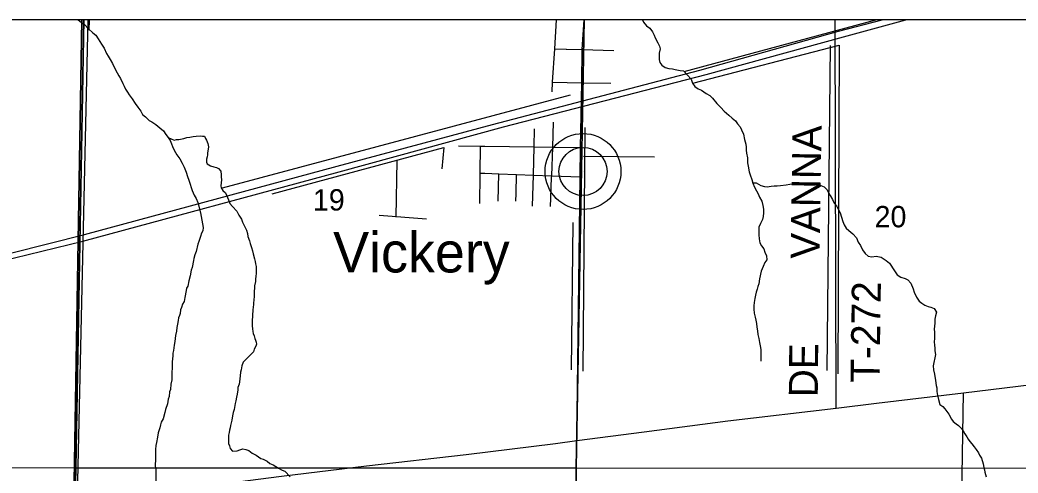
# Model space of a CAD drawing. Extents: x -8.5 to 18.7, y -20.3 to 7.
# Drawn here: x 11.462 to 15.375, y 5.162 to 6.938 of the extents above; entities that cross this region are included whole.
import ezdxf

# ---------------------------------------------------------------- set-up
doc = ezdxf.new("R2010")
doc.units = 0
for name, color, linetype in [('Default', 7, 'Continuous'), ('GM_X_Corporation', 7, 'Continuous'), ('GM_X_County_Road', 7, 'Continuous'), ('GM_X_Minor_River', 7, 'Continuous'), ('GM_X_Rail_Line', 7, 'Continuous'), ('GM_X_Section', 7, 'Continuous'), ('GM_X_Section_Text', 7, 'Continuous'), ('GM_X_State_Route', 7, 'Continuous'), ('GM_X_Township_Road', 7, 'Continuous'), ('GM_X_Township_Road_Text', 7, 'Continuous'), ('GM_X_Unincorporated', 7, 'Continuous'), ('GM_X_Unincorporated_Location', 7, 'Continuous'), ('GM_X_Unincorporated_Text', 7, 'Continuous'), ('SH_Cut_Line', 7, 'Continuous')]:
    doc.layers.add(name, color=color, linetype=linetype)

msp = doc.modelspace()

# ---------------------------------------------------------------- linework, layer by layer
at = {"layer": 'Default'}
for points in [[(11.7119, 6.938), (9.7054, 6.938), (9.6798, 5.1845), (11.681, 5.1825)], [(13.674, 6.938), (11.7119, 6.938), (11.681, 5.1825), (13.6421, 5.1822)], [(15.6554, 6.938), (13.674, 6.938), (13.6421, 5.1822), (15.6471, 5.1817)]]:
    msp.add_lwpolyline(points, close=True, dxfattribs=at)
at = {"layer": 'GM_X_Corporation'}
msp.add_lwpolyline([(3.6318, 1.1236), (5.043, 1.1473), (5.1251, 1.1484), (7.5383, 1.181), (7.59, 1.1818), (9.5569, 1.2131), (11.5871, 1.2389), (11.6132, 2.2462), (11.64, 3.2551), (11.6653, 4.2586), (11.6686, 4.5917), (11.6689, 4.6186), (11.6732, 5.0475), (11.7049, 6.938), (-0.1911, 6.938)], dxfattribs=at)
msp.add_lwpolyline([(18.7413, 1.1834), (18.7413, 6.938), (11.7049, 6.938), (11.6732, 5.0475), (11.6689, 4.6186), (11.6686, 4.5917), (11.6653, 4.2586), (11.64, 3.2551), (11.6132, 2.2462), (11.5871, 1.2389), (13.587, 1.2234), (15.5804, 1.208), (17.3261, 1.1944), (18.0915, 1.1885)], close=True, dxfattribs=at)
at = {"layer": 'GM_X_County_Road'}
for p, q in [((11.6869, 5.048), (11.7294, 6.938)), ((13.6358, 4.2197), (13.645, 5.2895))]:
    msp.add_line(p, q, dxfattribs=at)
msp.add_lwpolyline([(13.645, 5.2895), (13.6582, 6.3234), (13.6599, 6.4386), (13.6644, 6.6919), (13.6668, 6.8218), (13.6743, 6.938)], dxfattribs=at)
at = {"layer": 'GM_X_Minor_River'}
for p, q in [((11.7332, 6.8978), (11.7341, 6.938)), ((14.0662, 6.7359), (14.8175, 6.938)), ((14.0996, 6.69), (14.6734, 6.8391)), ((14.6265, 5.5642), (14.6405, 6.8383)), ((14.6734, 6.8391), (14.6682, 5.5509)), ((14.6734, 6.8391), (14.6734, 6.8391)), ((12.2558, 6.2802), (13.62, 6.6444)), ((13.67, 5.5617), (13.6786, 6.5159)), ((12.4511, 6.2567), (13.1239, 6.4386)), ((13.1239, 6.4386), (13.1165, 6.355)), ((13.1239, 6.4386), (13.1239, 6.4386)), ((12.9392, 6.3878), (12.9353, 6.1655)), ((13.6718, 6.4045), (13.95, 6.4014)), ((12.8702, 6.1733), (13.056, 6.1589)), ((13.624, 5.5667), (13.6312, 6.1439))]:
    msp.add_line(p, q, dxfattribs=at)
for points in [[(11.6893, 6.938), (11.7024, 6.9278), (11.7146, 6.9203), (11.7307, 6.9028), (11.7474, 6.887), (11.7589, 6.8779), (11.7688, 6.8635), (11.7818, 6.843), (11.7925, 6.8271), (11.801, 6.8067), (11.8071, 6.7961), (11.8148, 6.7824), (11.824, 6.7673), (11.8309, 6.7536), (11.8431, 6.7309), (11.8493, 6.7187), (11.8554, 6.7081), (11.8653, 6.6892), (11.87, 6.6786), (11.8761, 6.6664), (11.8837, 6.6551), (11.8899, 6.6445), (11.9013, 6.6286), (11.9128, 6.6104), (11.9235, 6.596), (11.935, 6.5801), (11.9426, 6.5679), (11.9533, 6.5581), (11.9678, 6.5445), (11.9792, 6.5385), (11.9945, 6.5279), (12.0097, 6.515), (12.0242, 6.5029), (12.0334, 6.4893), (12.0425, 6.4772)], [(13.9034, 6.938), (13.9069, 6.9296), (13.9184, 6.9152), (13.9313, 6.9061), (13.942, 6.8917), (13.9482, 6.8789), (13.9528, 6.8682), (13.9627, 6.8485), (13.9689, 6.8356), (13.972, 6.825), (13.9683, 6.8075), (13.9684, 6.7825), (13.9707, 6.7718), (13.9784, 6.7605), (13.9921, 6.7514), (14.0065, 6.7477), (14.0202, 6.7462), (14.0308, 6.744), (14.0506, 6.7403), (14.0635, 6.7388), (14.0795, 6.7214), (14.094, 6.7055), (14.0994, 6.6903), (14.1078, 6.6774), (14.1208, 6.6676), (14.1337, 6.6631), (14.152, 6.6502), (14.1665, 6.642), (14.1772, 6.6314), (14.1947, 6.6109), (14.21, 6.5943), (14.2237, 6.5806), (14.2413, 6.5648), (14.255, 6.5527), (14.2679, 6.5421), (14.2748, 6.5307), (14.2855, 6.5194), (14.2909, 6.508)], [(14.2909, 6.508), (14.2993, 6.4905), (14.3032, 6.4701), (14.3079, 6.4518), (14.3087, 6.4389), (14.3095, 6.4283), (14.3111, 6.4154), (14.3142, 6.3979), (14.3151, 6.3782), (14.3174, 6.3653), (14.3206, 6.3433), (14.3244, 6.3311), (14.3313, 6.3122), (14.336, 6.2985), (14.3421, 6.2833), (14.3498, 6.2689), (14.3567, 6.2568), (14.3621, 6.2432), (14.3705, 6.2272), (14.3751, 6.2113), (14.3767, 6.1961), (14.3776, 6.1825), (14.3754, 6.1673), (14.3731, 6.1558), (14.3649, 6.1399), (14.3596, 6.1262), (14.3589, 6.111), (14.359, 6.0958), (14.3606, 6.0798), (14.363, 6.0639), (14.3699, 6.0533), (14.3783, 6.0412), (14.3829, 6.0275), (14.389, 6.0139), (14.3899, 5.9979), (14.3831, 5.9873), (14.3756, 5.972), (14.3688, 5.9538), (14.3614, 5.9234), (14.3585, 5.9044), (14.3547, 5.8937), (14.3525, 5.8831), (14.348, 5.8709), (14.3458, 5.8595), (14.3428, 5.8458), (14.3406, 5.8306), (14.3399, 5.8177), (14.34, 5.804), (14.3408, 5.7888), (14.3447, 5.7729), (14.3478, 5.7608), (14.3494, 5.7478), (14.351, 5.7334), (14.3533, 5.7198), (14.3549, 5.7046), (14.3588, 5.6894), (14.3619, 5.6735), (14.3643, 5.6606), (14.3666, 5.6461), (14.3668, 5.6012)], [(12.0425, 6.4772), (12.0669, 6.4666), (12.0752, 6.469), (12.0851, 6.4698), (12.104, 6.4729), (12.1162, 6.4767), (12.1283, 6.479), (12.1412, 6.4814), (12.1526, 6.4822), (12.1678, 6.4845), (12.1776, 6.483), (12.1852, 6.4823), (12.1898, 6.474), (12.1929, 6.4664), (12.199, 6.4543), (12.2006, 6.4413), (12.1999, 6.4322), (12.1977, 6.417), (12.197, 6.4094), (12.1955, 6.4018), (12.1933, 6.3919), (12.1933, 6.3813), (12.1964, 6.3737), (12.2086, 6.3669), (12.2215, 6.3624), (12.2329, 6.3602), (12.2405, 6.3557), (12.2497, 6.3458), (12.2513, 6.3314), (12.2513, 6.3238), (12.2514, 6.3117), (12.2507, 6.2995), (12.25, 6.2881), (12.2508, 6.2797), (12.2577, 6.2699), (12.2676, 6.2601), (12.2722, 6.2517), (12.2799, 6.2328), (12.2845, 6.2183), (12.2952, 6.207), (12.312, 6.1888), (12.3158, 6.1813), (12.3204, 6.1729), (12.325, 6.1653), (12.3303, 6.157), (12.3342, 6.1456), (12.3411, 6.1327), (12.3495, 6.1145), (12.3534, 6.1016), (12.3557, 6.0895), (12.3619, 6.0721), (12.3642, 6.0614), (12.3696, 6.0463), (12.3735, 6.0334), (12.3758, 6.0212), (12.382, 6.0015), (12.3836, 5.9916), (12.3851, 5.9825), (12.3875, 5.9719), (12.3883, 5.9613), (12.3876, 5.943), (12.3869, 5.9347), (12.3854, 5.921), (12.3855, 5.9126), (12.3818, 5.8959), (12.3818, 5.8868), (12.3804, 5.8746), (12.3796, 5.867), (12.3797, 5.8564), (12.3783, 5.8382), (12.3776, 5.8306), (12.3768, 5.8222), (12.3754, 5.8024), (12.3747, 5.7948), (12.3732, 5.7865), (12.3733, 5.7766), (12.3718, 5.7599), (12.3719, 5.7485), (12.3727, 5.7394), (12.3735, 5.7272), (12.3743, 5.7174), (12.3766, 5.7098), (12.3805, 5.6999), (12.3828, 5.6901), (12.3859, 5.6825), (12.3882, 5.6749), (12.389, 5.6673), (12.386, 5.6597), (12.38, 5.6475), (12.3778, 5.6369)], [(12.0425, 6.4772), (12.0509, 6.4651), (12.0563, 6.4529), (12.0602, 6.4416), (12.0663, 6.4279), (12.077, 6.4097), (12.0885, 6.3931), (12.0977, 6.3771), (12.1054, 6.3605), (12.1131, 6.3415), (12.1185, 6.3248), (12.1238, 6.3104), (12.1285, 6.2945), (12.1331, 6.2808), (12.137, 6.2702), (12.1446, 6.2512), (12.1523, 6.2383), (12.1592, 6.2224), (12.1694, 6.1823)], [(14.3354, 6.3001), (14.3489, 6.3001), (14.3664, 6.2895), (14.3808, 6.2858), (14.3922, 6.2843), (14.4074, 6.2866), (14.4188, 6.2874), (14.4309, 6.2875), (14.4438, 6.2891), (14.4666, 6.2922), (14.481, 6.2938), (14.4931, 6.2953), (14.5053, 6.2954), (14.5311, 6.297), (14.5425, 6.294), (14.5531, 6.2933), (14.5668, 6.2926), (14.5797, 6.2926), (14.5911, 6.2919), (14.6025, 6.2889), (14.6154, 6.2836), (14.6261, 6.2731), (14.6322, 6.2624), (14.6384, 6.2503), (14.6475, 6.2344), (14.6544, 6.22), (14.6636, 6.2094), (14.672, 6.1942), (14.6774, 6.1821), (14.6836, 6.1647), (14.6882, 6.1487), (14.6936, 6.1351), (14.7012, 6.1222), (14.7119, 6.1131), (14.7279, 6.1003), (14.7424, 6.0836), (14.7486, 6.0677), (14.7578, 6.054), (14.7654, 6.0374), (14.7761, 6.0222), (14.7876, 6.0116), (14.802, 6.0094), (14.8187, 6.0125), (14.8392, 6.008), (14.8583, 5.9952), (14.8712, 5.9854), (14.8911, 5.9551), (14.9011, 5.9391), (14.9155, 5.9293), (14.9323, 5.9241), (14.9429, 5.9196), (14.9551, 5.9067), (14.9643, 5.8847), (14.9682, 5.871), (14.9774, 5.8521), (14.9874, 5.8362), (14.998, 5.8286), (15.0102, 5.8203), (15.0232, 5.815), (15.0338, 5.812), (15.0467, 5.8075), (15.0552, 5.7931), (15.0522, 5.7787), (15.0492, 5.765), (15.0485, 5.7498), (15.0478, 5.7377), (15.0471, 5.7263), (15.048, 5.7149), (15.0472, 5.7042), (15.0473, 5.689), (15.0466, 5.6769), (15.0482, 5.664), (15.049, 5.6518), (15.0498, 5.6412), (15.0514, 5.6275)], [(12.1694, 6.1823), (12.1805, 6.1241), (12.1783, 6.112), (12.1738, 6.1021), (12.1693, 6.0899), (12.1633, 6.0701), (12.1596, 6.0587), (12.1521, 6.0306), (12.1469, 6.0169), (12.1439, 6.0032), (12.1417, 5.9948), (12.1373, 5.9682), (12.1328, 5.9575), (12.1291, 5.9347), (12.1239, 5.9157), (12.1194, 5.8952), (12.1149, 5.8868), (12.1134, 5.8777), (12.1082, 5.8503), (12.1053, 5.8343), (12.0993, 5.8237), (12.0955, 5.8107), (12.0918, 5.8016), (12.0903, 5.7879), (12.0873, 5.7795), (12.0836, 5.7712), (12.0821, 5.7605), (12.0792, 5.7461), (12.0769, 5.7324), (12.0755, 5.7187), (12.0718, 5.7012), (12.0689, 5.6784), (12.0659, 5.6639), (12.0637, 5.6419), (12.0615, 5.632), (12.0608, 5.6221), (12.0593, 5.61), (12.0586, 5.5986), (12.0588, 5.575), (12.0573, 5.5568), (12.0574, 5.5461), (12.0567, 5.5378), (12.0567, 5.5279), (12.0538, 5.5104), (12.0516, 5.4899), (12.0486, 5.4808), (12.0472, 5.4618), (12.0434, 5.4519), (12.042, 5.4427), (12.0405, 5.4329), (12.033, 5.4115), (12.03, 5.4001), (12.0233, 5.3743), (12.0158, 5.3613), (12.0128, 5.3507), (12.0106, 5.34), (12.0039, 5.3202), (12.0009, 5.3035), (11.9972, 5.2815), (11.9942, 5.2708), (11.9936, 5.2541), (11.9937, 5.2343), (11.993, 5.2093), (11.9916, 5.1994), (11.9916, 5.1887), (11.9947, 5.1774), (11.995, 5.1257)], [(12.3778, 5.6369), (12.3373, 5.5969), (12.332, 5.5824), (12.3291, 5.5664), (12.3268, 5.5581), (12.3239, 5.5307), (12.321, 5.5109), (12.3165, 5.4972), (12.3158, 5.4881), (12.3128, 5.4714), (12.3106, 5.46), (12.3084, 5.4448), (12.3054, 5.4349), (12.301, 5.4113), (12.2973, 5.3999), (12.2951, 5.3862), (12.2929, 5.3695), (12.2899, 5.3588), (12.2869, 5.3489), (12.2854, 5.3398), (12.2832, 5.3299), (12.2817, 5.3208), (12.2795, 5.3109), (12.2788, 5.301), (12.2788, 5.2904), (12.2796, 5.2782), (12.2827, 5.2684), (12.2866, 5.2585), (12.2957, 5.2479), (12.3132, 5.2488), (12.3238, 5.2526), (12.3352, 5.2565), (12.3473, 5.255), (12.3595, 5.2505), (12.3717, 5.2407), (12.3884, 5.2324), (12.4067, 5.2196), (12.4159, 5.2166), (12.4311, 5.2083), (12.4418, 5.2), (12.4547, 5.194), (12.4752, 5.1812), (12.4905, 5.1729), (12.5004, 5.1691), (12.521, 5.148)], [(15.0514, 5.6275), (15.0431, 5.583), (15.0439, 5.5663), (15.0478, 5.5504), (15.0517, 5.5246), (15.0548, 5.5056), (15.0564, 5.4965), (15.0572, 5.4828), (15.0588, 5.4722), (15.0604, 5.4623), (15.0635, 5.4502), (15.0689, 5.4312), (15.0811, 5.4229), (15.0879, 5.4138), (15.0956, 5.4032), (15.104, 5.3934), (15.1147, 5.3737), (15.1216, 5.3646), (15.133, 5.3548), (15.1422, 5.348), (15.1536, 5.3366), (15.1605, 5.3276), (15.1674, 5.3162), (15.175, 5.3041), (15.1796, 5.295), (15.1858, 5.2859), (15.1942, 5.2761), (15.2033, 5.2655), (15.2117, 5.2541), (15.2201, 5.2412), (15.2247, 5.2329), (15.2316, 5.22), (15.2386, 5.198), (15.2417, 5.1836), (15.2433, 5.1752), (15.2456, 5.1661), (15.251, 5.1472)]]:
    msp.add_lwpolyline(points, dxfattribs=at)
at = {"layer": 'GM_X_Rail_Line'}
for points in [[(3.3492, 3.6263), (4.4113, 3.9753), (4.8681, 4.1485), (5.3383, 4.3406), (5.8491, 4.5056), (6.1923, 4.6193), (6.6809, 4.7548), (6.9366, 4.825), (7.6892, 5.0264), (8.5879, 5.2635), (9.4613, 5.4827), (11.0096, 5.9016), (11.7084, 6.0715), (12.7137, 6.343), (13.3579, 6.5187), (14.1524, 6.7238), (14.6912, 6.8722), (14.936, 6.938)], [(3.8129, 4.1403), (4.3242, 4.207), (4.4317, 4.2229), (4.6591, 4.2738), (5.1343, 4.3961), (5.6672, 4.5409), (6.9377, 4.8691), (7.6692, 5.0633), (8.6247, 5.3078), (9.4518, 5.5207), (10.9979, 5.9173), (11.7143, 6.0969), (12.7059, 6.3644), (13.315, 6.5285), (14.1271, 6.7413), (14.6717, 6.8937), (14.8429, 6.938)]]:
    msp.add_lwpolyline(points, dxfattribs=at)
at = {"layer": 'GM_X_Section'}
for points in [[(11.681, 5.1825), (11.6384, 3.2557), (9.6423, 3.2228), (9.6798, 5.1845)], [(13.6421, 5.1822), (13.6222, 3.2394), (11.6384, 3.2557), (11.681, 5.1825)], [(15.6471, 5.1817), (15.6347, 3.2252), (13.6222, 3.2394), (13.6421, 5.1822)]]:
    msp.add_lwpolyline(points, close=True, dxfattribs=at)
at = {"layer": 'GM_X_State_Route'}
msp.add_lwpolyline([(10.687, 4.9287), (10.7287, 4.9346), (10.9024, 4.9549), (11.2577, 4.9986), (11.5812, 5.0354), (11.6736, 5.0464), (11.6869, 5.048), (12.1416, 5.1052), (12.4869, 5.1498), (12.8209, 5.1899), (13.2111, 5.2354), (13.5617, 5.2783), (13.645, 5.2895), (13.909, 5.3237), (14.2377, 5.3664), (14.6621, 5.4171), (14.8198, 5.4359), (15.1611, 5.4766), (15.4293, 5.5094), (15.6511, 5.5375), (15.667, 5.5395)], dxfattribs=at)
at = {"layer": 'GM_X_Township_Road'}
for p, q in [((14.6621, 5.4171), (14.6589, 6.938)), ((13.5587, 6.8253), (13.6029, 6.8239)), ((13.6668, 6.8218), (13.7909, 6.8178)), ((13.5505, 6.6938), (13.6644, 6.6919)), ((13.6644, 6.6919), (13.7783, 6.6901)), ((13.2649, 6.2188), (13.266, 6.3313)), ((13.266, 6.3376), (13.285, 6.3369)), ((13.3365, 6.2273), (13.3392, 6.335)), ((13.4073, 6.2574), (13.4091, 6.3324)), ((13.5437, 6.24), (13.5466, 6.3225)), ((13.4065, 6.2273), (13.4073, 6.2574)), ((13.5426, 6.207), (13.5437, 6.24)), ((15.1413, 4.2248), (15.1611, 5.4766))]:
    msp.add_line(p, q, dxfattribs=at)
for points in [[(13.5482, 6.6566), (13.5505, 6.6938), (13.5587, 6.8253), (13.5659, 6.938)], [(13.6029, 6.8239), (13.6052, 6.8238), (13.6668, 6.8218)], [(13.5466, 6.3225), (13.5467, 6.3274), (13.5506, 6.44), (13.5539, 6.5371)], [(13.4718, 6.2077), (13.4748, 6.3301), (13.4774, 6.441), (13.4791, 6.5112)], [(13.181, 6.4449), (13.267, 6.4437), (13.2851, 6.4435)], [(13.266, 6.3313), (13.266, 6.3376), (13.267, 6.4437)], [(13.2851, 6.4435), (13.4774, 6.441), (13.5506, 6.44), (13.6599, 6.4386)], [(13.285, 6.3369), (13.3392, 6.335), (13.4091, 6.3324), (13.4748, 6.3301), (13.5467, 6.3274), (13.6582, 6.3234)]]:
    msp.add_lwpolyline(points, dxfattribs=at)
at = {"layer": 'GM_X_Unincorporated'}
for radius in [0.1488, 0.0943]:
    msp.add_circle((13.6696, 6.3441), radius, dxfattribs=at)
at = {"layer": 'GM_X_Unincorporated_Location'}
msp.add_line((13.6696, 6.3441), (13.6696, 6.3441), dxfattribs=at)
at = {"layer": 'SH_Cut_Line'}
msp.add_lwpolyline([(18.7413, -10.9039), (18.7413, 6.938), (-8.4587, 6.938)], dxfattribs=at)

# ---------------------------------------------------------------- texts
at = {"layer": 'GM_X_Section_Text'}
for s, p in [('19', (12.6106, 6.1911)), ('20', (14.8131, 6.1253))]:
    msp.add_text(s, height=0.08371, rotation=0, dxfattribs=at).set_placement(p)
at = {"layer": 'GM_X_Township_Road_Text'}
for s, rotation, p in [('VANNA', 89.0787, (14.5968, 6.0009)), ('T-272', 89.1569, (14.832, 5.5156)), ('DE', 89.4841, (14.5901, 5.4589))]:
    msp.add_text(s, height=0.11364, rotation=rotation, dxfattribs=at).set_placement(p)
at = {"layer": 'GM_X_Unincorporated_Text'}
msp.add_text('Vickery', height=0.15795, rotation=0, dxfattribs=at).set_placement((12.6898, 5.9484))

doc.saveas('drawing.dxf')
